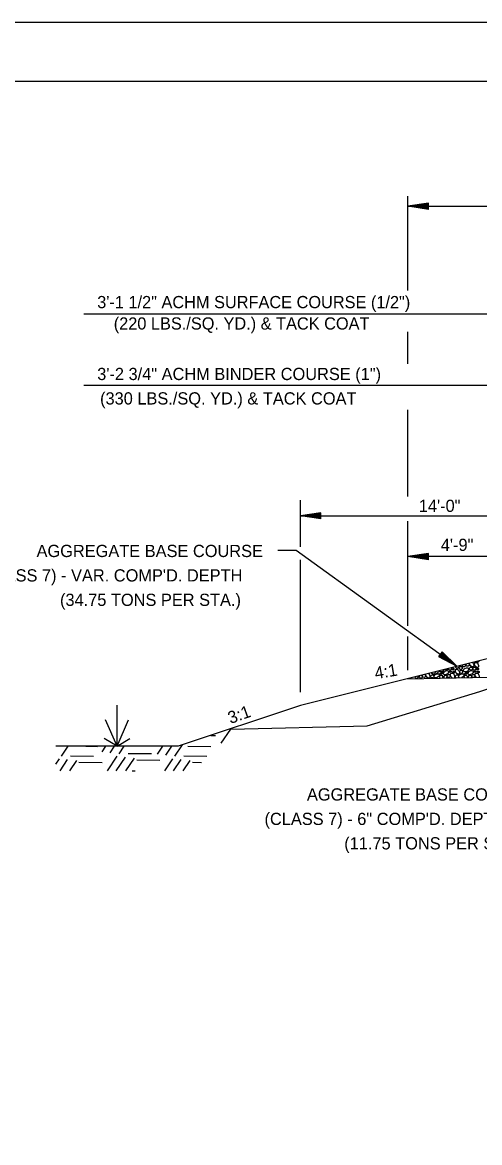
# Model space of a CAD drawing. Extents: x 2478 to 3210, y 439 to 841.
# Drawn here: x 2951.1 to 2996, y 548.6 to 658.6 of the extents above; entities that cross this region are included whole.
import ezdxf

# ---------------------------------------------------------------- set-up
doc = ezdxf.new("R2010")
doc.units = 0
for name, color, linetype in [('1', 7, 'Continuous'), ('R_Annotation', 7, 'Continuous'), ('R_Dimension', 7, 'Continuous'), ('R_Draft', 7, 'Continuous'), ('R_Exist Surface', 7, 'Continuous')]:
    doc.layers.add(name, color=color, linetype=linetype)

msp = doc.modelspace()

# ---------------------------------------------------------------- linework, layer by layer
at = {"layer": '1'}
msp.add_line((2885.53, 652.81), (3204.6, 652.81), dxfattribs=at)
for points in [[(3210.37, 658.58), (2870.37, 658.58), (2870.37, 438.58), (3210.37, 438.58)], [(2885.53, 444.35), (2885.53, 652.81), (3122.34, 652.81), (3122.34, 642.93), (3161.5, 642.93), (3161.5, 640.01), (3204.6, 640.01), (3204.6, 444.35)]]:
    msp.add_lwpolyline(points, close=True, dxfattribs=at)
at = {"layer": 'R_Annotation'}
for p, q in [((2998.39, 596.5), (2978.39, 591.5)), ((2988.93, 594.13), (3008.39, 594.52)), ((2978.39, 591.5), (2966.39, 587.5)), ((2966.39, 587.5), (2954.39, 587.5))]:
    msp.add_line(p, q, dxfattribs=at)
at = {"layer": 'R_Dimension'}
for p, q in [((2988.93, 632.26), (2988.93, 641.52)), ((2990.93, 640.82), (2988.93, 640.52)), ((2988.93, 640.52), (3067.85, 640.52)), ((2990.93, 640.22), (2988.93, 640.52)), ((2990.93, 640.77), (2989.26, 640.52)), ((2990.93, 640.27), (2989.26, 640.52)), ((2990.93, 640.72), (2989.61, 640.52)), ((2990.93, 640.32), (2989.61, 640.52)), ((2990.93, 640.67), (2989.94, 640.52)), ((2990.93, 640.37), (2989.94, 640.52)), ((2990.93, 640.62), (2990.28, 640.52)), ((2990.93, 640.42), (2990.28, 640.52)), ((2990.93, 640.57), (2990.61, 640.52)), ((2990.93, 640.47), (2990.61, 640.52)), ((2990.93, 640.22), (2990.93, 640.82)), ((3008.39, 629.93), (2957.14, 629.93)), ((2988.93, 625.06), (2988.93, 628.2)), ((3008.39, 622.94), (2957.14, 622.94)), ((2988.93, 612.02), (2988.93, 620.54)), ((2978.39, 607.09), (2978.39, 611.68)), ((2980.39, 610.42), (2978.39, 610.12)), ((2978.39, 610.12), (3006.39, 610.12)), ((2980.39, 609.82), (2978.39, 610.12)), ((2980.39, 610.37), (2978.72, 610.12)), ((2980.39, 609.87), (2978.72, 610.12)), ((2980.39, 610.32), (2979.06, 610.12)), ((2980.39, 609.93), (2979.06, 610.12)), ((2980.39, 610.27), (2979.4, 610.12)), ((2980.39, 609.98), (2979.4, 610.12)), ((2980.39, 610.22), (2979.74, 610.12)), ((2980.39, 610.03), (2979.74, 610.12)), ((2980.39, 610.17), (2980.07, 610.12)), ((2980.39, 610.08), (2980.07, 610.12)), ((2980.39, 609.82), (2980.39, 610.42)), ((2988.93, 599.32), (2988.93, 609.62)), ((2990.93, 606.42), (2988.93, 606.12)), ((3067.85, 606.12), (2988.93, 606.12)), ((2990.93, 605.82), (2988.93, 606.12)), ((2990.93, 606.37), (2989.27, 606.12)), ((2990.93, 605.87), (2989.27, 606.12)), ((2990.93, 606.32), (2989.61, 606.12)), ((2990.93, 605.93), (2989.61, 606.12)), ((2990.93, 606.27), (2989.94, 606.12)), ((2990.93, 605.98), (2989.94, 606.12)), ((2990.93, 606.22), (2990.28, 606.12)), ((2990.93, 606.03), (2990.28, 606.12)), ((2990.93, 606.17), (2990.62, 606.12)), ((2990.93, 606.08), (2990.62, 606.12)), ((2990.93, 605.82), (2990.93, 606.42)), ((2978.39, 592.82), (2978.39, 605.82)), ((2988.93, 594.96), (2988.93, 598.29)), ((2992.28, 596.78), (2991.93, 596.3)), ((2991.93, 596.3), (2993.72, 595.37)), ((2991.96, 596.34), (2993.45, 595.56)), ((2991.99, 596.38), (2993.17, 595.77)), ((2992.02, 596.42), (2992.9, 595.96)), ((2992.05, 596.46), (2992.63, 596.16)), ((2992.08, 596.5), (2992.36, 596.35)), ((2992.13, 596.58), (2992.36, 596.35)), ((2992.16, 596.62), (2992.63, 596.16)), ((2992.19, 596.66), (2992.9, 595.96)), ((2992.22, 596.7), (2993.17, 595.77)), ((2992.25, 596.74), (2993.45, 595.56)), ((2992.28, 596.78), (2993.72, 595.37)), ((2994.63, 595.53), (2994.66, 595.57)), ((2995.27, 595.72), (2995.32, 595.66)), ((2990.03, 594.35), (2990.08, 594.42)), ((2990.35, 594.43), (2990.39, 594.5)), ((2994.46, 594.24), (2994.44, 594.33)), ((2994.88, 594.25), (2994.86, 594.35)), ((2969.6, 588.57), (2970.05, 588.56)), ((2970.61, 587.79), (2971.55, 589.18)), ((2954.94, 586.52), (2955.59, 587.5)), ((2957.33, 587.5), (2958.48, 587.49)), ((2958.92, 586.95), (2959.29, 587.5)), ((2959.72, 586.86), (2960.15, 587.5)), ((2960.61, 586.76), (2961.1, 587.5)), ((2964.37, 586.71), (2964.9, 587.5)), ((2965.17, 586.62), (2965.76, 587.5)), ((2966.06, 586.52), (2966.81, 587.64)), ((2967.34, 587.51), (2969.6, 587.49)), ((2955.83, 586.56), (2958.09, 586.54)), ((2959.46, 585.09), (2960.42, 586.52)), ((2960.32, 585.09), (2961.22, 586.43)), ((2961.27, 585.09), (2962.11, 586.34)), ((2961.5, 586.8), (2963.76, 586.78)), ((2966.95, 586.56), (2969.21, 586.54)), ((2954.39, 585.74), (2954.75, 586.28)), ((2954.81, 585.09), (2955.55, 586.19)), ((2955.76, 585.09), (2956.44, 586.1)), ((2956.66, 585.93), (2958.92, 585.91)), ((2962.33, 586.17), (2964.59, 586.15)), ((2965.07, 585.09), (2965.87, 586.28)), ((2965.93, 585.09), (2966.67, 586.19)), ((2966.88, 585.09), (2967.56, 586.1)), ((2967.78, 585.93), (2968.67, 585.92)), ((2961.89, 585.1), (2962.16, 585.09))]:
    msp.add_line(p, q, dxfattribs=at)
for points in [[(2976.15, 606.75), (2977.95, 606.75), (2993.72, 595.37)], [(2992.84, 595.11), (2992.83, 595.05), (2992.75, 594.98), (2992.62, 594.99), (2992.56, 595.04)], [(2993.17, 595.19), (2993.18, 595.18), (2993.16, 595.04), (2993.09, 594.98), (2992.96, 594.99), (2992.9, 595.05), (2992.88, 595.12)], [(2993.25, 595.11), (2993.3, 595.18), (2993.37, 595.18), (2993.43, 595.13), (2993.42, 595.05), (2993.37, 595.02), (2993.29, 595.02), (2993.26, 595.05), (2993.25, 595.11)], [(2993.38, 595.25), (2993.37, 595.23), (2993.33, 595.23)], [(2993.89, 595.37), (2993.91, 595.35), (2993.9, 595.23), (2993.81, 595.16), (2993.69, 595.16), (2993.63, 595.23), (2993.61, 595.3)], [(2993.95, 595.21), (2994.03, 595.33), (2994.17, 595.34), (2994.25, 595.24), (2994.24, 595.11), (2994.16, 595.04), (2994.03, 595.05), (2993.97, 595.11), (2993.95, 595.21)], [(2994.07, 595.42), (2994.04, 595.39), (2993.98, 595.4)], [(2994.53, 595.53), (2994.55, 595.49), (2994.53, 595.35), (2994.47, 595.29), (2994.36, 595.29), (2994.23, 595.39), (2994.2, 595.45)], [(2994.51, 595.14), (2994.66, 595.2), (2994.79, 595.19), (2994.86, 595.13), (2994.86, 595.02), (2994.76, 594.89), (2994.6, 594.81), (2994.46, 594.81), (2994.37, 594.86), (2994.36, 594.98), (2994.43, 595.09), (2994.51, 595.15)], [(2994.88, 595.62), (2994.94, 595.56), (2994.92, 595.43), (2994.84, 595.37), (2994.71, 595.37), (2994.65, 595.43), (2994.63, 595.53)], [(2994.96, 595.15), (2995.03, 595.27), (2995.17, 595.27), (2995.26, 595.18), (2995.25, 595.05), (2995.16, 594.98), (2995.03, 594.99), (2994.97, 595.05), (2994.96, 595.15)], [(2995.32, 595.67), (2995.38, 595.51), (2995.36, 595.37), (2995.3, 595.3), (2995.18, 595.31), (2995.06, 595.41), (2994.97, 595.57), (2994.97, 595.64)], [(2995.29, 595.15), (2995.38, 595.26), (2995.5, 595.27), (2995.6, 595.18), (2995.58, 595.04), (2995.5, 594.98), (2995.37, 594.99), (2995.32, 595.05), (2995.29, 595.15)], [(2995.79, 595.59), (2995.85, 595.44), (2995.84, 595.3), (2995.78, 595.23), (2995.67, 595.24), (2995.54, 595.34), (2995.46, 595.49), (2995.46, 595.64), (2995.51, 595.72), (2995.63, 595.73), (2995.74, 595.66), (2995.8, 595.58)], [(2995.88, 595.87), (2995.88, 595.82), (2995.8, 595.76), (2995.67, 595.76), (2995.62, 595.81)], [(2995.66, 595.11), (2995.72, 595.18), (2995.79, 595.18), (2995.84, 595.13), (2995.84, 595.05), (2995.79, 595.02), (2995.71, 595.02), (2995.67, 595.05), (2995.66, 595.11)], [(2989.33, 594.23), (2989.32, 594.23), (2989.3, 594.23)], [(2989.9, 594.38), (2989.91, 594.37), (2989.9, 594.24), (2989.82, 594.17), (2989.69, 594.18), (2989.63, 594.24), (2989.61, 594.3)], [(2990.25, 594.46), (2990.33, 594.37), (2990.31, 594.24), (2990.24, 594.18), (2990.11, 594.19), (2990.05, 594.25), (2990.03, 594.35)], [(2990.57, 594.54), (2990.65, 594.46), (2990.63, 594.33), (2990.55, 594.26), (2990.42, 594.27), (2990.36, 594.33), (2990.35, 594.43)], [(2991.02, 594.55), (2991.08, 594.41), (2991.07, 594.26), (2991.01, 594.2), (2990.9, 594.2), (2990.77, 594.3), (2990.69, 594.45), (2990.68, 594.57)], [(2990.95, 594.64), (2990.97, 594.63), (2991.03, 594.55)], [(2991.16, 594.38), (2991.25, 594.5), (2991.38, 594.5), (2991.46, 594.41), (2991.45, 594.28), (2991.37, 594.21), (2991.25, 594.22), (2991.18, 594.28), (2991.16, 594.38)], [(2991.56, 594.79), (2991.56, 594.79), (2991.55, 594.65), (2991.49, 594.58), (2991.38, 594.58), (2991.25, 594.68), (2991.24, 594.71)], [(2991.63, 594.56), (2991.78, 594.62), (2991.92, 594.61), (2991.99, 594.55), (2991.99, 594.43), (2991.88, 594.31), (2991.73, 594.23), (2991.58, 594.22), (2991.5, 594.28), (2991.5, 594.4), (2991.56, 594.5), (2991.64, 594.57)], [(2991.87, 594.87), (2991.88, 594.86), (2991.86, 594.73), (2991.78, 594.66), (2991.65, 594.67), (2991.59, 594.73), (2991.58, 594.8)], [(2992.44, 595.01), (2992.35, 594.89), (2992.19, 594.81), (2992.04, 594.81), (2991.95, 594.86), (2991.95, 594.89)], [(2992.02, 594.35), (2992.11, 594.46), (2992.24, 594.47), (2992.32, 594.37), (2992.31, 594.24), (2992.27, 594.2)], [(2992.09, 594.2), (2992.05, 594.24), (2992.02, 594.33)], [(2992.03, 594.6), (2992.08, 594.66), (2992.16, 594.67), (2992.21, 594.61), (2992.2, 594.53), (2992.16, 594.49), (2992.08, 594.5), (2992.04, 594.54), (2992.03, 594.6)], [(2992.2, 594.74), (2992.25, 594.8), (2992.32, 594.81), (2992.38, 594.75), (2992.37, 594.68), (2992.32, 594.63), (2992.25, 594.64), (2992.21, 594.68), (2992.2, 594.74)], [(2992.56, 594.87), (2992.71, 594.93), (2992.85, 594.92), (2992.92, 594.86), (2992.92, 594.74), (2992.82, 594.61), (2992.66, 594.54), (2992.51, 594.53), (2992.43, 594.59), (2992.42, 594.71), (2992.49, 594.81), (2992.57, 594.87)], [(2992.44, 594.35), (2992.53, 594.46), (2992.66, 594.47), (2992.75, 594.37), (2992.73, 594.24), (2992.69, 594.21)], [(2992.51, 594.2), (2992.47, 594.25), (2992.44, 594.35)], [(2992.76, 594.43), (2992.84, 594.54), (2992.97, 594.55), (2993.07, 594.46), (2993.05, 594.33), (2992.97, 594.26), (2992.84, 594.27), (2992.78, 594.33), (2992.76, 594.43)], [(2992.99, 594.87), (2993.04, 594.94), (2993.13, 594.94), (2993.18, 594.89), (2993.16, 594.81), (2993.12, 594.77), (2993.04, 594.77), (2993.01, 594.81), (2992.99, 594.87)], [(2993.28, 594.22), (2993.18, 594.3), (2993.1, 594.45), (2993.1, 594.6), (2993.16, 594.68), (2993.27, 594.69), (2993.38, 594.63), (2993.45, 594.55)], [(2993.32, 594.81), (2993.37, 594.88), (2993.45, 594.89), (2993.5, 594.83), (2993.49, 594.75), (2993.44, 594.71), (2993.37, 594.72), (2993.33, 594.75), (2993.32, 594.81)], [(2993.44, 594.55), (2993.5, 594.41), (2993.49, 594.26), (2993.45, 594.22)], [(2993.92, 594.93), (2993.98, 594.79), (2993.97, 594.65), (2993.91, 594.58), (2993.79, 594.58), (2993.67, 594.68), (2993.58, 594.84), (2993.58, 594.98), (2993.64, 595.07), (2993.76, 595.08), (2993.86, 595.01), (2993.92, 594.93)], [(2993.58, 594.38), (2993.66, 594.5), (2993.79, 594.5), (2993.87, 594.41), (2993.86, 594.28), (2993.81, 594.23)], [(2993.66, 594.23), (2993.59, 594.28), (2993.58, 594.38)], [(2993.98, 594.23), (2993.92, 594.28), (2993.91, 594.4), (2993.98, 594.5), (2994.05, 594.57)], [(2993.99, 594.83), (2994.07, 594.95), (2994.2, 594.96), (2994.29, 594.86), (2994.28, 594.73), (2994.19, 594.66), (2994.07, 594.67), (2994.01, 594.73), (2993.99, 594.83)], [(2994.04, 594.56), (2994.19, 594.62), (2994.34, 594.61), (2994.41, 594.55), (2994.4, 594.43), (2994.3, 594.31), (2994.17, 594.24)], [(2994.44, 594.6), (2994.49, 594.66), (2994.57, 594.67), (2994.63, 594.61), (2994.62, 594.53), (2994.57, 594.49), (2994.49, 594.5), (2994.46, 594.54), (2994.44, 594.6)], [(2994.44, 594.35), (2994.52, 594.46), (2994.65, 594.47), (2994.74, 594.37), (2994.73, 594.25)], [(2994.61, 594.74), (2994.66, 594.8), (2994.74, 594.81), (2994.79, 594.75), (2994.79, 594.68), (2994.74, 594.63), (2994.66, 594.64), (2994.63, 594.68), (2994.61, 594.74)], [(2994.97, 594.87), (2995.13, 594.93), (2995.27, 594.92), (2995.33, 594.86), (2995.33, 594.74), (2995.23, 594.61), (2995.07, 594.54), (2994.92, 594.53), (2994.84, 594.59), (2994.84, 594.71), (2994.9, 594.81), (2994.98, 594.87)], [(2994.86, 594.35), (2994.94, 594.46), (2995.07, 594.47), (2995.16, 594.37), (2995.14, 594.26)], [(2995.18, 594.43), (2995.25, 594.54), (2995.39, 594.55), (2995.48, 594.46), (2995.46, 594.33), (2995.38, 594.26), (2995.25, 594.27), (2995.19, 594.33), (2995.18, 594.43)], [(2995.41, 594.87), (2995.46, 594.94), (2995.54, 594.94), (2995.6, 594.89), (2995.58, 594.81), (2995.53, 594.77), (2995.46, 594.77), (2995.43, 594.81), (2995.41, 594.87)], [(2995.64, 594.27), (2995.6, 594.3), (2995.52, 594.45), (2995.51, 594.6), (2995.57, 594.68), (2995.69, 594.69), (2995.8, 594.63), (2995.86, 594.55)], [(2995.73, 594.81), (2995.78, 594.88), (2995.86, 594.89), (2995.91, 594.83), (2995.9, 594.75), (2995.85, 594.71), (2995.78, 594.72), (2995.74, 594.75), (2995.73, 594.81)], [(2995.85, 594.55), (2995.91, 594.41), (2995.9, 594.27)]]:
    msp.add_lwpolyline(points, dxfattribs=at)
at = {"layer": 'R_Draft'}
for q in [(2960.39, 591.52), (2959.25, 590.08), (2961.53, 590.08), (2959.13, 588.26), (2961.64, 588.26)]:
    msp.add_line((2960.39, 587.5), q, dxfattribs=at)
at = {"layer": 'R_Exist Surface'}
msp.add_lwpolyline([(2971.55, 589.18), (2984.94, 589.49), (2995.98, 592.89), (3003.21, 595.33), (3006.45, 596.34), (3028.39, 596.92), (3047.8, 596.44), (3050.6, 596.33), (3058.49, 595.31), (3072.68, 592.77), (3086.17, 594.04)], dxfattribs=at)

# ---------------------------------------------------------------- texts
at = {"layer": 'R_Annotation'}
for s, height, p in [('3\'-1 1/2" ACHM SURFACE COURSE (1/2")', 1.197, (2958.45, 630.52)), ('(220 LBS./SQ. YD.) & TACK COAT', 1.197, (2960.07, 628.42)), ('3\'-2 3/4" ACHM BINDER COURSE (1")', 1.2, (2958.45, 623.46)), ('(330 LBS./SQ. YD.) & TACK COAT', 1.2, (2958.73, 621.06)), ('14\'-0"', 1.2, (2989.99, 610.51)), ('AGGREGATE BASE COURSE', 1.2, (2952.5, 606.08)), ('4\'-9"', 1.2, (2992.15, 606.68)), ("(CLASS 7) - VAR. COMP'D. DEPTH", 1.2, (2946.79, 603.68)), ('(34.75 TONS PER STA.)', 1.2, (2954.8, 601.28)), ('AGGREGATE BASE COURSE', 1.2, (2979.02, 582.17)), ('(CLASS 7) - 6" COMP\'D. DEPTH', 1.2, (2974.86, 579.77)), ('(11.75 TONS PER STA.)', 1.2, (2982.68, 577.37))]:
    msp.add_text(s, height=height, dxfattribs=at).set_placement(p)
for s, rotation, p in [('4:1', 9.5754, (2985.76, 594.08)), ('3:1', 19.6286, (2971.52, 589.68))]:
    msp.add_text(s, height=1.2, rotation=rotation, dxfattribs=at).set_placement(p)

doc.saveas('drawing.dxf')
